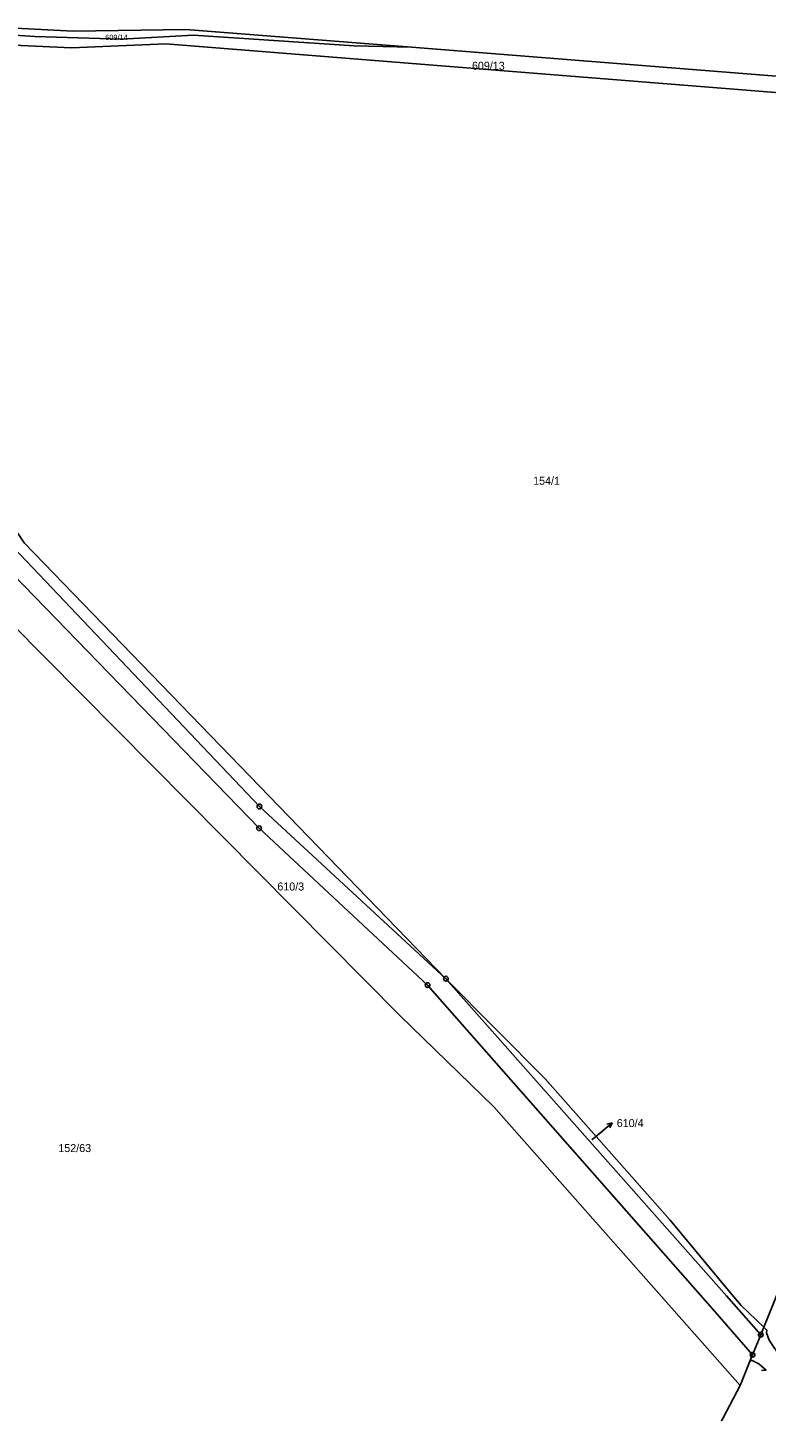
# Model space of a CAD drawing. Extents: x -783948 to -781889, y -1005870 to -1004430.
# Drawn here: x -783223.5 to -783066.7, y -1004810.4 to -1004516.5 of the extents above; entities that cross this region are included whole.
import ezdxf

# ---------------------------------------------------------------- set-up
doc = ezdxf.new("R2010")
doc.units = 0
for name, color, linetype in [('Vrstva 1', 7, 'Continuous'), ('Vrstva 2', 7, 'Continuous'), ('Vrstva 4', 7, 'Continuous'), ('Vrstva 7', 7, 'Continuous'), ('Vrstva 8', 7, 'Continuous')]:
    doc.layers.add(name, color=color, linetype=linetype)

msp = doc.modelspace()

# ---------------------------------------------------------------- linework, layer by layer
at = {"layer": 'Vrstva 1'}
for p, q in [((-783067.86, -1004794.15), (-783067.21, -1004792.53)), ((-783069.58, -1004798.4), (-783067.86, -1004794.15)), ((-783072.24, -1004804.97), (-783070.08, -1004799.63)), ((-783070.08, -1004799.63), (-783069.58, -1004798.4))]:
    msp.add_line(p, q, dxfattribs=at)
for points in [[(-783227.44, -1004516.53), (-783213.82, -1004517.27), (-783189.9, -1004516.91), (-783142, -1004520.7)], [(-783260.49, -1004518.65), (-783279.95, -1004521.52), (-783274.36, -1004541.26), (-783262.05, -1004566.99), (-783246.27, -1004593.28), (-783224.23, -1004625.98), (-783134.69, -1004718.53)], [(-782952.59, -1004544.91), (-783045.16, -1004531.87), (-783194.17, -1004519.95), (-783214.2, -1004520.81), (-783251.02, -1004519.09)], [(-783142, -1004520.7), (-783154.21, -1004520.36), (-783188.29, -1004518.14), (-783203.6, -1004518.94), (-783221.97, -1004518.38), (-783227.34, -1004518.05)], [(-783142, -1004520.7), (-783042.27, -1004528.59), (-782966.43, -1004538.99)], [(-783297.41, -1004528.44), (-783286.71, -1004544.64), (-783276.24, -1004564.44), (-783255.93, -1004595.99), (-783174.29, -1004681.96), (-783134.69, -1004718.53)], [(-783067.21, -1004792.53), (-783063.9, -1004784.36), (-783061.96, -1004780.66), (-783050.23, -1004759.6), (-783038.28, -1004738.39), (-783028.73, -1004721.42), (-783009.37, -1004685.85), (-782999.99, -1004667.33), (-782992.05, -1004650.2), (-782977.93, -1004618.08), (-782962.45, -1004577.29), (-782955.84, -1004558.52)], [(-783069.58, -1004798.4), (-783078.12, -1004788.69), (-783138.61, -1004719.9), (-783174.36, -1004686.59), (-783256.21, -1004602.15)], [(-783234.73, -1004635.33), (-783144.5, -1004726.36), (-783124.55, -1004745.73), (-783072.24, -1004804.97)], [(-783134.69, -1004718.53), (-783075.13, -1004785.92), (-783067.86, -1004794.15)], [(-783134.69, -1004718.53), (-783113.64, -1004739.8), (-783087.12, -1004769.86), (-783074.38, -1004785.22)], [(-783074.38, -1004785.22), (-783072.02, -1004787.95), (-783067.21, -1004792.53)], [(-783067.21, -1004792.53), (-783066.53, -1004793.18), (-783066.65, -1004793.77), (-783066.08, -1004795.34), (-783063.58, -1004798.99)], [(-783066.67, -1004801.71), (-783068.29, -1004800.32), (-783069.64, -1004799.61), (-783070.08, -1004799.63)], [(-783131.09, -1004916.54), (-783125.4, -1004904.88), (-783114.97, -1004885.18), (-783105.38, -1004866.4), (-783094.69, -1004847.64), (-783072.24, -1004804.97)]]:
    msp.add_lwpolyline(points, dxfattribs=at)
at = {"layer": 'Vrstva 4'}
msp.add_line((-783067.67, -1004801.74), (-783066.67, -1004801.71), dxfattribs=at)
at = {"layer": 'Vrstva 7'}
for p, q in [((-783101.73, -1004751.11), (-783099.43, -1004749.18)), ((-783099.43, -1004749.18), (-783100.52, -1004749.44)), ((-783099.43, -1004749.18), (-783099.88, -1004750.21)), ((-783103.73, -1004752.77), (-783101.73, -1004751.11))]:
    msp.add_line(p, q, dxfattribs=at)
at = {"layer": 'Vrstva 8'}
for centre, radius in [((-783174.29, -1004681.96), 0.5), ((-783174.29, -1004681.96), 0.0303), ((-783174.36, -1004686.59), 0.5), ((-783174.36, -1004686.59), 0.0303), ((-783138.61, -1004719.9), 0.5), ((-783138.61, -1004719.9), 0.0303), ((-783134.69, -1004718.53), 0.5), ((-783134.69, -1004718.53), 0.0303), ((-783067.86, -1004794.15), 0.5), ((-783067.86, -1004794.15), 0.0303), ((-783069.58, -1004798.4), 0.5), ((-783069.58, -1004798.4), 0.0303)]:
    msp.add_circle(centre, radius, dxfattribs=at)

# ---------------------------------------------------------------- texts
at = {"layer": 'Vrstva 2'}
for s, height, p in [('609/14', 1.14, (-783207.06, -1004519.17)), ('609/13', 1.7, (-783129.17, -1004525.47)), ('154/1', 1.7, (-783116.18, -1004613.62)), ('610/3', 1.7, (-783170.49, -1004699.8)), ('610/4', 1.7, (-783098.42, -1004750.05)), ('152/63', 1.7, (-783216.99, -1004755.36))]:
    msp.add_text(s, height=height, dxfattribs=at).set_placement(p)

doc.saveas('drawing.dxf')
